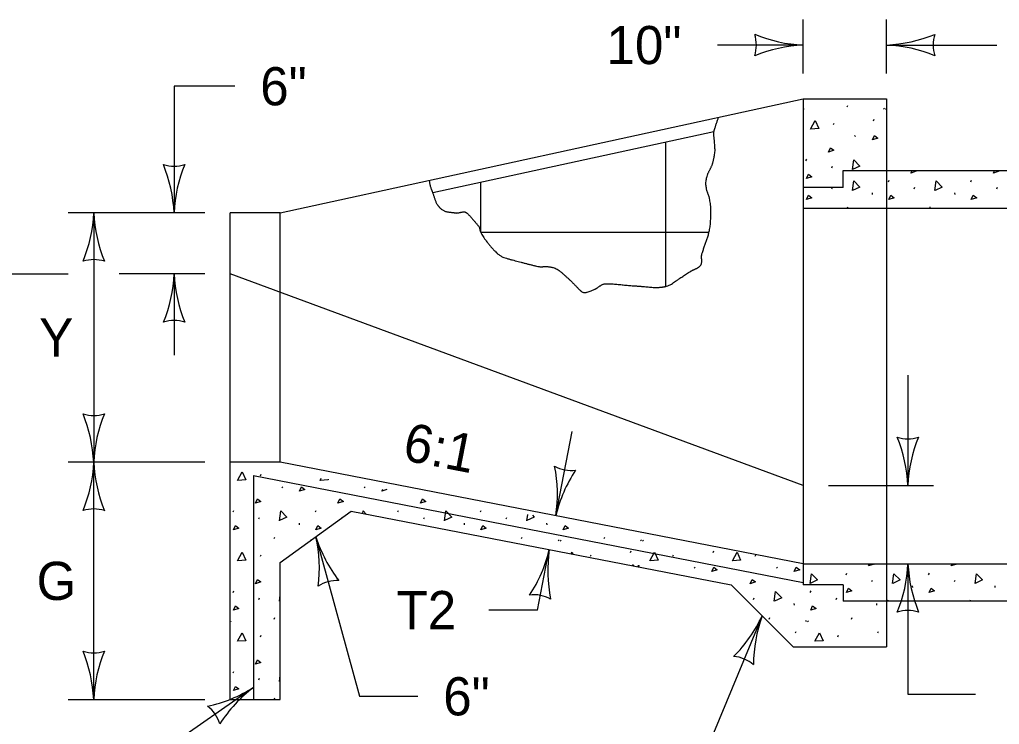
# Model space of a CAD drawing. Extents: x 49991.4 to 50043, y 49987.6 to 50011.4.
# Drawn here: x 50002.892 to 50004.432, y 49997.154 to 49998.262 of the extents above; entities that cross this region are included whole.
import ezdxf

# ---------------------------------------------------------------- set-up
doc = ezdxf.new("R2010")
doc.units = 0
for name, color, linetype in [('Level 1', 7, 'Continuous'), ('Level 2', 7, 'Continuous'), ('Level 3', 7, 'Continuous'), ('Level 4', 7, 'Continuous')]:
    doc.layers.add(name, color=color, linetype=linetype)

msp = doc.modelspace()

# ---------------------------------------------------------------- linework, layer by layer
at = {"layer": 'Level 1'}
for p, q in [((50003.3015, 49997.9582), (50004.1233, 49998.1373)), ((50004.1233, 49998.1373), (50004.2543, 49998.1373)), ((50004.1233, 49998.1373), (50004.1233, 49997.3739)), ((50004.2543, 49998.1373), (50004.2543, 49997.2761)), ((50004.1233, 49998.1222), (50004.1244, 49998.1206)), ((50004.1926, 49998.1248), (50004.1936, 49998.1272)), ((50004.2498, 49998.1228), (50004.2509, 49998.1212)), ((50004.2529, 49998.1222), (50004.254, 49998.1206)), ((50004.2341, 49998.1031), (50004.2352, 49998.1055)), ((50004.171, 49998.097), (50004.1721, 49998.0994)), ((50003.9832, 49998.0858), (50003.5411, 49997.9898)), ((50004.2043, 49998.0799), (50004.2054, 49998.0783)), ((50003.9068, 49998.0692), (50003.9068, 49997.8425)), ((50004.1278, 49998.0402), (50004.1289, 49998.0426)), ((50004.1683, 49998.0293), (50004.1694, 49998.0317)), ((50004.1865, 49997.9984), (50004.1865, 49998.0246)), ((50004.1865, 49998.0246), (50004.877, 49998.0246)), ((50003.6164, 49998.0056), (50003.6164, 49997.9281)), ((50004.1865, 49997.9984), (50004.1233, 49997.9984)), ((50004.1683, 49997.9963), (50004.1693, 49997.9984)), ((50004.2574, 49998.0072), (50004.2585, 49998.0096)), ((50004.2979, 49997.9963), (50004.299, 49997.9987)), ((50004.3871, 49998.0072), (50004.3881, 49998.0096)), ((50004.4275, 49997.9963), (50004.4286, 49997.9987)), ((50004.2317, 49997.9896), (50004.2319, 49997.9872)), ((50004.3613, 49997.9896), (50004.3615, 49997.9872)), ((50004.9129, 49997.9654), (50004.1233, 49997.9654)), ((50004.1926, 49997.9654), (50004.1936, 49997.9678)), ((50004.3222, 49997.9654), (50004.3232, 49997.9678)), ((50003.2228, 49997.1935), (50003.2228, 49997.9582)), ((50003.3015, 49997.9582), (50003.2228, 49997.9582)), ((50003.6164, 49997.9281), (50003.9754, 49997.9281)), ((50002.638, 49997.8625), (50002.9684, 49997.8625)), ((50004.1233, 49997.5297), (50003.2228, 49997.8625)), ((50003.3015, 49997.5663), (50003.2228, 49997.5663)), ((50004.1233, 49997.4069), (50003.3015, 49997.5663)), ((50003.2594, 49997.5453), (50004.1233, 49997.3773)), ((50003.2594, 49997.5453), (50003.2594, 49997.1935)), ((50003.2705, 49997.545), (50003.2716, 49997.5474)), ((50003.3038, 49997.5279), (50003.3049, 49997.5263)), ((50003.4334, 49997.5279), (50003.4345, 49997.5263)), ((50003.2273, 49997.4882), (50003.2284, 49997.4906)), ((50003.3015, 49997.4089), (50003.413, 49997.4895)), ((50003.3569, 49997.4882), (50003.358, 49997.4906)), ((50003.413, 49997.4895), (50004.0102, 49997.3737)), ((50003.4866, 49997.4882), (50003.4876, 49997.4906)), ((50003.6162, 49997.4882), (50003.6172, 49997.4906)), ((50003.2678, 49997.4773), (50003.2689, 49997.4797)), ((50003.398, 49997.4787), (50003.3985, 49997.4797)), ((50003.527, 49997.4773), (50003.5281, 49997.4797)), ((50003.6567, 49997.4773), (50003.6577, 49997.4797)), ((50003.3312, 49997.4706), (50003.3314, 49997.4682)), ((50003.5904, 49997.4706), (50003.5907, 49997.4682)), ((50003.72, 49997.4706), (50003.7203, 49997.4682)), ((50003.2921, 49997.4464), (50003.2931, 49997.4488)), ((50003.3493, 49997.4444), (50003.3497, 49997.4438)), ((50003.6809, 49997.4464), (50003.682, 49997.4488)), ((50003.7382, 49997.4444), (50003.7393, 49997.4428)), ((50003.7413, 49997.4438), (50003.7423, 49997.4422)), ((50003.8105, 49997.4464), (50003.8116, 49997.4488)), ((50003.8678, 49997.4444), (50003.8689, 49997.4428)), ((50003.8709, 49997.4438), (50003.8719, 49997.4422)), ((50003.8521, 49997.4246), (50003.8531, 49997.427)), ((50003.9817, 49997.4246), (50003.9828, 49997.427)), ((50003.2705, 49997.4185), (50003.2716, 49997.4209)), ((50003.7889, 49997.4185), (50003.79, 49997.4209)), ((50003.9186, 49997.4185), (50003.9196, 49997.4209)), ((50004.0482, 49997.4185), (50004.0492, 49997.4209)), ((50003.3015, 49997.1935), (50003.3015, 49997.4089)), ((50003.8553, 49997.4049), (50003.8555, 49997.4037)), ((50003.8573, 49997.4033), (50003.8553, 49997.4049)), ((50003.9519, 49997.4015), (50003.9529, 49997.3999)), ((50004.0815, 49997.4015), (50004.0825, 49997.3999)), ((50004.1233, 49997.4069), (50004.848, 49997.4069)), ((50004.191, 49997.3896), (50004.1921, 49997.392)), ((50004.2315, 49997.3787), (50004.2326, 49997.3811)), ((50004.3206, 49997.3896), (50004.3217, 49997.392)), ((50004.3611, 49997.3787), (50004.3622, 49997.3811)), ((50003.2273, 49997.3618), (50003.2284, 49997.3642)), ((50004.0102, 49997.3737), (50004.1075, 49997.2761)), ((50004.1865, 49997.3739), (50004.1233, 49997.3739)), ((50004.1346, 49997.3618), (50004.1357, 49997.3642)), ((50004.1865, 49997.3739), (50004.1865, 49997.3478)), ((50004.2949, 49997.372), (50004.2951, 49997.3696)), ((50004.4245, 49997.372), (50004.4247, 49997.3696)), ((50003.2678, 49997.3508), (50003.2689, 49997.3532)), ((50004.0455, 49997.3508), (50004.0466, 49997.3532)), ((50004.1751, 49997.3508), (50004.1762, 49997.3532)), ((50004.2558, 49997.3478), (50004.2568, 49997.3502)), ((50004.3854, 49997.3478), (50004.3864, 49997.3502)), ((50004.1088, 49997.3442), (50004.1091, 49997.3418)), ((50004.8771, 49997.3478), (50004.1865, 49997.3478)), ((50004.2385, 49997.3442), (50004.2387, 49997.3418)), ((50003.2921, 49997.3199), (50003.2931, 49997.3223)), ((50004.0697, 49997.3199), (50004.0708, 49997.3223)), ((50004.127, 49997.3179), (50004.1281, 49997.3163)), ((50004.1301, 49997.3173), (50004.1312, 49997.3157)), ((50004.1994, 49997.3199), (50004.2004, 49997.3223)), ((50003.2234, 49997.3164), (50003.2239, 49997.3157)), ((50003.2705, 49997.2921), (50003.2716, 49997.2945)), ((50004.1113, 49997.2982), (50004.1124, 49997.3006)), ((50004.1778, 49997.2921), (50004.1788, 49997.2945)), ((50004.2409, 49997.2982), (50004.242, 49997.3006)), ((50004.1075, 49997.2761), (50004.2543, 49997.2761)), ((50003.2273, 49997.2353), (50003.2284, 49997.2377)), ((50003.2678, 49997.2244), (50003.2689, 49997.2268)), ((50003.2921, 49997.1935), (50003.2931, 49997.1959)), ((50003.2228, 49997.1935), (50003.3015, 49997.1935))]:
    msp.add_line(p, q, dxfattribs=at)
for points in [[(50004.135, 49998.0898), (50004.1422, 49998.1034), (50004.1478, 49998.0908), (50004.1353, 49998.0898)], [(50004.2323, 49998.073), (50004.2355, 49998.0797), (50004.2408, 49998.0757), (50004.2323, 49998.073)], [(50004.163, 49998.0539), (50004.1662, 49998.0606), (50004.1716, 49998.0566), (50004.163, 49998.0539)], [(50004.2007, 49998.0265), (50004.2028, 49998.0418), (50004.2124, 49998.0319), (50004.201, 49998.0266)], [(50004.1284, 49998.0123), (50004.1316, 49998.0189), (50004.1369, 49998.0149), (50004.1284, 49998.0123)], [(50004.2927, 49998.0209), (50004.2945, 49998.0246)], [(50004.2999, 49998.0246), (50004.3012, 49998.0236), (50004.2927, 49998.0209)], [(50004.4223, 49998.0209), (50004.4241, 49998.0246)], [(50004.4295, 49998.0246), (50004.4308, 49998.0236), (50004.4223, 49998.0209)], [(50004.2007, 49997.9935), (50004.2028, 49998.0088), (50004.2124, 49997.9989), (50004.201, 49997.9936)], [(50004.3303, 49997.9935), (50004.3325, 49998.0088), (50004.342, 49997.9989), (50004.3306, 49997.9936)], [(50004.1284, 49997.9793), (50004.1316, 49997.9859), (50004.1369, 49997.9819), (50004.1284, 49997.9793)], [(50004.258, 49997.9793), (50004.2612, 49997.9859), (50004.2665, 49997.9819), (50004.258, 49997.9793)], [(50004.3876, 49997.9793), (50004.3908, 49997.9859), (50004.3961, 49997.9819), (50004.3876, 49997.9793)], [(50003.2345, 49997.5378), (50003.2417, 49997.5514), (50003.2473, 49997.5388), (50003.2348, 49997.5378)], [(50003.3641, 49997.5378), (50003.366, 49997.5414)], [(50003.3766, 49997.5395), (50003.3769, 49997.5388), (50003.3644, 49997.5378)], [(50003.3318, 49997.521), (50003.335, 49997.5276), (50003.3403, 49997.5236), (50003.3318, 49997.521)], [(50003.4614, 49997.521), (50003.463, 49997.5243)], [(50003.4689, 49997.5233), (50003.4614, 49997.521)], [(50003.2625, 49997.5019), (50003.2657, 49997.5086), (50003.2711, 49997.5046), (50003.2625, 49997.5019)], [(50003.3922, 49997.5019), (50003.3954, 49997.5086), (50003.4007, 49997.5046), (50003.3922, 49997.5019)], [(50003.5218, 49997.5019), (50003.525, 49997.5086), (50003.5303, 49997.5046), (50003.5218, 49997.5019)], [(50003.3002, 49997.4745), (50003.3023, 49997.4898), (50003.3119, 49997.4799), (50003.3005, 49997.4746)], [(50003.4314, 49997.4859), (50003.432, 49997.4898), (50003.4367, 49997.4849)], [(50003.5595, 49997.4745), (50003.5616, 49997.4898), (50003.5711, 49997.4799), (50003.5597, 49997.4746)], [(50003.6891, 49997.4745), (50003.6904, 49997.4842)], [(50003.6978, 49997.483), (50003.7007, 49997.4799), (50003.6893, 49997.4746)], [(50003.2279, 49997.4602), (50003.2311, 49997.4669), (50003.2364, 49997.4629), (50003.2279, 49997.4602)], [(50003.3575, 49997.4602), (50003.3607, 49997.4669), (50003.366, 49997.4629), (50003.3575, 49997.4602)], [(50003.6167, 49997.4602), (50003.6199, 49997.4669), (50003.6252, 49997.4629), (50003.6167, 49997.4602)], [(50003.7463, 49997.4602), (50003.7495, 49997.4669), (50003.7548, 49997.4629), (50003.7463, 49997.4602)], [(50003.2345, 49997.4113), (50003.2417, 49997.4249), (50003.2473, 49997.4124), (50003.2348, 49997.4113)], [(50003.7589, 49997.4224), (50003.7602, 49997.4249), (50003.7615, 49997.4219)], [(50003.8826, 49997.4113), (50003.8898, 49997.4249), (50003.8954, 49997.4124), (50003.8829, 49997.4113)], [(50004.0122, 49997.4113), (50004.0194, 49997.4249), (50004.025, 49997.4124), (50004.0125, 49997.4113)], [(50003.9798, 49997.3945), (50003.983, 49997.4012), (50003.9883, 49997.3972), (50003.9798, 49997.3945)], [(50004.1094, 49997.3945), (50004.1126, 49997.4012), (50004.118, 49997.3972), (50004.1094, 49997.3945)], [(50004.2262, 49997.4033), (50004.2279, 49997.4069)], [(50004.2336, 49997.4069), (50004.2348, 49997.406), (50004.2262, 49997.4033)], [(50004.3559, 49997.4033), (50004.3576, 49997.4069)], [(50004.3632, 49997.4069), (50004.3644, 49997.406), (50004.3559, 49997.4033)], [(50003.2625, 49997.3755), (50003.2657, 49997.3822), (50003.2711, 49997.3782), (50003.2625, 49997.3755)], [(50004.0402, 49997.3755), (50004.0434, 49997.3822), (50004.0487, 49997.3782), (50004.0402, 49997.3755)], [(50004.1343, 49997.3759), (50004.1364, 49997.3912), (50004.146, 49997.3813), (50004.1346, 49997.376)], [(50004.2639, 49997.3759), (50004.266, 49997.3912), (50004.2756, 49997.3813), (50004.2642, 49997.376)], [(50004.3935, 49997.3759), (50004.3957, 49997.3912), (50004.4052, 49997.3813), (50004.3938, 49997.376)], [(50004.1916, 49997.3617), (50004.1948, 49997.3683), (50004.2001, 49997.3643), (50004.1916, 49997.3617)], [(50004.3212, 49997.3617), (50004.3244, 49997.3683), (50004.3297, 49997.3643), (50004.3212, 49997.3617)], [(50003.3002, 49997.3481), (50003.3015, 49997.3575)], [(50003.3015, 49997.3487), (50003.3005, 49997.3482)], [(50004.0779, 49997.3481), (50004.08, 49997.3633), (50004.0896, 49997.3535), (50004.0782, 49997.3482)], [(50003.2279, 49997.3338), (50003.2311, 49997.3405), (50003.2364, 49997.3365), (50003.2279, 49997.3338)], [(50004.1352, 49997.3338), (50004.1383, 49997.3405), (50004.1437, 49997.3365), (50004.1352, 49997.3338)], [(50003.2345, 49997.2849), (50003.2417, 49997.2985), (50003.2473, 49997.2859), (50003.2348, 49997.2849)], [(50004.1418, 49997.2849), (50004.149, 49997.2985), (50004.1546, 49997.2859), (50004.1421, 49997.2849)], [(50003.2625, 49997.249), (50003.2657, 49997.2557), (50003.2711, 49997.2517), (50003.2625, 49997.249)], [(50003.3002, 49997.2216), (50003.3015, 49997.2311)], [(50003.2279, 49997.2074), (50003.2311, 49997.214), (50003.2364, 49997.21), (50003.2279, 49997.2074)], [(50003.3015, 49997.2222), (50003.3005, 49997.2217)]]:
    msp.add_lwpolyline(points, dxfattribs=at)
msp.add_arc((50003.8648, 49997.4025), 0.00126, 318.786, 199.2662, dxfattribs=at)
msp.add_open_spline([(50003.5356, 49998.0092), (50003.5359, 49998.0075), (50003.5362, 49998.0057), (50003.5365, 49998.0039), (50003.5369, 49998.0015), (50003.5376, 49997.9991), (50003.5385, 49997.9968), (50003.5389, 49997.9956), (50003.5394, 49997.9945), (50003.5398, 49997.9933), (50003.5402, 49997.9922), (50003.5407, 49997.991), (50003.5411, 49997.9898), (50003.5419, 49997.9877), (50003.5425, 49997.9856), (50003.5432, 49997.9835), (50003.5439, 49997.9814), (50003.5446, 49997.9794), (50003.5454, 49997.9773), (50003.5462, 49997.9752), (50003.5472, 49997.9732), (50003.5484, 49997.9713), (50003.549, 49997.9703), (50003.5497, 49997.9694), (50003.5504, 49997.9685), (50003.5508, 49997.968), (50003.5512, 49997.9675), (50003.5516, 49997.9671), (50003.552, 49997.9666), (50003.5524, 49997.9662), (50003.5529, 49997.9657), (50003.5545, 49997.9641), (50003.5564, 49997.9629), (50003.5584, 49997.9619), (50003.5604, 49997.9609), (50003.5624, 49997.9603), (50003.5645, 49997.9599), (50003.5666, 49997.9596), (50003.5687, 49997.9593), (50003.5708, 49997.959), (50003.5718, 49997.9589), (50003.5729, 49997.9588), (50003.574, 49997.9587), (50003.575, 49997.9585), (50003.5761, 49997.9583), (50003.5771, 49997.9582), (50003.5786, 49997.958), (50003.5801, 49997.9582), (50003.5816, 49997.9584), (50003.5831, 49997.9586), (50003.5847, 49997.9591), (50003.5862, 49997.9593), (50003.5877, 49997.9596), (50003.5892, 49997.9597), (50003.5907, 49997.9597), (50003.5914, 49997.9597), (50003.592, 49997.9596), (50003.5927, 49997.9593), (50003.5934, 49997.959), (50003.594, 49997.9587), (50003.5946, 49997.9582), (50003.5967, 49997.9564), (50003.5986, 49997.9545), (50003.6004, 49997.9525), (50003.6022, 49997.9504), (50003.6038, 49997.9483), (50003.6056, 49997.9463), (50003.607, 49997.9448), (50003.6083, 49997.9432), (50003.6097, 49997.9416), (50003.611, 49997.9401), (50003.6123, 49997.9385), (50003.6136, 49997.9368), (50003.6141, 49997.9362), (50003.6144, 49997.9355), (50003.6146, 49997.9348), (50003.6148, 49997.9341), (50003.615, 49997.9333), (50003.6152, 49997.9326), (50003.6153, 49997.9318), (50003.6154, 49997.931), (50003.6156, 49997.9303), (50003.6158, 49997.9295), (50003.6161, 49997.9288), (50003.6164, 49997.9281), (50003.6182, 49997.9244), (50003.6203, 49997.921), (50003.6227, 49997.9177), (50003.6252, 49997.9143), (50003.6277, 49997.911), (50003.6303, 49997.9078), (50003.6335, 49997.9039), (50003.6369, 49997.9002), (50003.6405, 49997.8965), (50003.6422, 49997.8948), (50003.6441, 49997.8933), (50003.6462, 49997.8919), (50003.6482, 49997.8905), (50003.6504, 49997.8893), (50003.6527, 49997.8885), (50003.6572, 49997.887), (50003.6617, 49997.8855), (50003.6663, 49997.8843), (50003.6709, 49997.8831), (50003.6754, 49997.8819), (50003.68, 49997.8807), (50003.6848, 49997.8795), (50003.6897, 49997.8782), (50003.6945, 49997.877), (50003.6993, 49997.8758), (50003.7041, 49997.8747), (50003.709, 49997.8736), (50003.7099, 49997.8734), (50003.7107, 49997.8734), (50003.7116, 49997.8734), (50003.7125, 49997.8735), (50003.7134, 49997.8736), (50003.7143, 49997.8737), (50003.7152, 49997.8738), (50003.7161, 49997.874), (50003.7169, 49997.8741), (50003.7178, 49997.8742), (50003.7187, 49997.8742), (50003.7196, 49997.8741), (50003.7214, 49997.874), (50003.7231, 49997.8737), (50003.7249, 49997.8734), (50003.7267, 49997.8731), (50003.7284, 49997.8727), (50003.7301, 49997.8723), (50003.7336, 49997.8713), (50003.7369, 49997.8698), (50003.7398, 49997.8676), (50003.7436, 49997.8647), (50003.7471, 49997.8617), (50003.7505, 49997.8585), (50003.7539, 49997.8554), (50003.7572, 49997.8523), (50003.7605, 49997.8491), (50003.7617, 49997.8479), (50003.7629, 49997.8467), (50003.7641, 49997.8455), (50003.7653, 49997.8443), (50003.7664, 49997.843), (50003.7676, 49997.8417), (50003.7694, 49997.8399), (50003.7712, 49997.838), (50003.773, 49997.8363), (50003.7734, 49997.836), (50003.7737, 49997.8358), (50003.774, 49997.8355), (50003.7743, 49997.8352), (50003.7746, 49997.835), (50003.775, 49997.8347), (50003.7764, 49997.8337), (50003.778, 49997.8332), (50003.7796, 49997.8332), (50003.7814, 49997.8331), (50003.7832, 49997.8334), (50003.785, 49997.834), (50003.7886, 49997.8353), (50003.7921, 49997.8367), (50003.7956, 49997.8382), (50003.7963, 49997.8385), (50003.7971, 49997.8389), (50003.7978, 49997.8392), (50003.7985, 49997.8396), (50003.7992, 49997.8401), (50003.7999, 49997.8405), (50003.8013, 49997.8414), (50003.8026, 49997.8424), (50003.804, 49997.8434), (50003.8054, 49997.8443), (50003.8067, 49997.8451), (50003.8082, 49997.8458), (50003.8097, 49997.8465), (50003.8112, 49997.8469), (50003.8128, 49997.8469), (50003.8168, 49997.847), (50003.8208, 49997.8469), (50003.8248, 49997.8465), (50003.8287, 49997.8462), (50003.8327, 49997.8459), (50003.8367, 49997.8455), (50003.8407, 49997.8451), (50003.8447, 49997.8446), (50003.8487, 49997.8443), (50003.8527, 49997.844), (50003.8567, 49997.8437), (50003.8607, 49997.8434), (50003.8626, 49997.8433), (50003.8645, 49997.8432), (50003.8665, 49997.843), (50003.8684, 49997.8429), (50003.8703, 49997.8427), (50003.8722, 49997.8425), (50003.8761, 49997.8422), (50003.8799, 49997.8418), (50003.8838, 49997.8414), (50003.8876, 49997.8411), (50003.8915, 49997.841), (50003.8953, 49997.8411), (50003.8972, 49997.8412), (50003.8992, 49997.8413), (50003.9011, 49997.8416), (50003.902, 49997.8417), (50003.903, 49997.8418), (50003.9039, 49997.842), (50003.9044, 49997.842), (50003.9049, 49997.8421), (50003.9054, 49997.8422), (50003.9058, 49997.8423), (50003.9063, 49997.8424), (50003.9068, 49997.8425), (50003.9107, 49997.8435), (50003.9145, 49997.8453), (50003.9179, 49997.8475), (50003.9213, 49997.8498), (50003.9246, 49997.8521), (50003.928, 49997.8544), (50003.934, 49997.8584), (50003.94, 49997.8625), (50003.9461, 49997.8663), (50003.9473, 49997.8671), (50003.9487, 49997.8677), (50003.95, 49997.8684), (50003.9513, 49997.869), (50003.9527, 49997.8695), (50003.954, 49997.8701), (50003.9554, 49997.8707), (50003.9567, 49997.8714), (50003.9579, 49997.8721), (50003.9586, 49997.8725), (50003.9592, 49997.873), (50003.9598, 49997.8734), (50003.9601, 49997.8737), (50003.9604, 49997.8739), (50003.9607, 49997.8742), (50003.961, 49997.8745), (50003.9612, 49997.8747), (50003.9615, 49997.875), (50003.9625, 49997.8762), (50003.9633, 49997.8776), (50003.9636, 49997.8791), (50003.9639, 49997.8807), (50003.964, 49997.8822), (50003.9639, 49997.8838), (50003.9639, 49997.8854), (50003.9637, 49997.887), (50003.9637, 49997.8887), (50003.9637, 49997.8895), (50003.9637, 49997.8903), (50003.9638, 49997.891), (50003.9639, 49997.8918), (50003.964, 49997.8926), (50003.9642, 49997.8933), (50003.9651, 49997.8962), (50003.966, 49997.8991), (50003.967, 49997.902), (50003.968, 49997.9048), (50003.969, 49997.9077), (50003.9701, 49997.9106), (50003.9711, 49997.9134), (50003.972, 49997.9163), (50003.973, 49997.9192), (50003.974, 49997.9221), (50003.9747, 49997.9251), (50003.9754, 49997.9281), (50003.9772, 49997.9361), (50003.9779, 49997.9442), (50003.9782, 49997.9522), (50003.9785, 49997.9615), (50003.978, 49997.9709), (50003.9764, 49997.9801), (50003.9762, 49997.9815), (50003.9759, 49997.9828), (50003.9754, 49997.984), (50003.975, 49997.9853), (50003.9745, 49997.9866), (50003.974, 49997.9879), (50003.9736, 49997.9891), (50003.9731, 49997.9904), (50003.9726, 49997.9917), (50003.9721, 49997.9929), (50003.9718, 49997.9942), (50003.9716, 49997.9955), (50003.9704, 49998.0024), (50003.9707, 49998.0097), (50003.9726, 49998.0165), (50003.9731, 49998.0183), (50003.9737, 49998.02), (50003.9745, 49998.0216), (50003.9753, 49998.0233), (50003.9761, 49998.0249), (50003.977, 49998.0265), (50003.9778, 49998.0282), (50003.9786, 49998.0298), (50003.9794, 49998.0315), (50003.9803, 49998.0331), (50003.9808, 49998.0349), (50003.9813, 49998.0366), (50003.9818, 49998.0385), (50003.9823, 49998.0404), (50003.9827, 49998.0423), (50003.9831, 49998.0442), (50003.9836, 49998.0461), (50003.9839, 49998.048), (50003.9846, 49998.0519), (50003.985, 49998.0557), (50003.9848, 49998.0595), (50003.9846, 49998.0638), (50003.9842, 49998.068), (50003.9839, 49998.0722), (50003.9836, 49998.0768), (50003.9827, 49998.0814), (50003.9832, 49998.0859), (50003.9833, 49998.0864), (50003.9834, 49998.0869), (50003.9836, 49998.0874), (50003.9837, 49998.0878), (50003.9838, 49998.0883), (50003.984, 49998.0888), (50003.9842, 49998.0898), (50003.9845, 49998.0907), (50003.9848, 49998.0917), (50003.9854, 49998.0935), (50003.986, 49998.0954), (50003.9867, 49998.0973), (50003.9879, 49998.101), (50003.9892, 49998.1047), (50003.9905, 49998.1084)], degree=3, dxfattribs=at)
at = {"layer": 'Level 3'}
for p, q in [((50004.1233, 49998.1773), (50004.1233, 49998.262)), ((50004.2543, 49998.1773), (50004.2543, 49998.262)), ((50004.1233, 49998.222), (50003.989, 49998.222)), ((50004.2543, 49998.222), (50004.4277, 49998.222)), ((50003.1347, 49998.1573), (50003.1347, 49997.9582)), ((50003.2301, 49998.1573), (50003.1347, 49998.1573)), ((50003.1828, 49997.9582), (50002.9684, 49997.9582)), ((50003.0084, 49997.9582), (50003.0084, 49997.5663)), ((50003.1828, 49997.8625), (50003.0484, 49997.8625)), ((50003.1347, 49997.8625), (50003.1347, 49997.7345)), ((50004.288, 49997.7032), (50004.288, 49997.5297)), ((50003.7347, 49997.4823), (50003.7605, 49997.6149)), ((50003.1828, 49997.5663), (50002.9684, 49997.5663)), ((50003.0084, 49997.1935), (50003.0084, 49997.5663)), ((50004.1633, 49997.5297), (50004.328, 49997.5297)), ((50003.3573, 49997.4493), (50003.4261, 49997.1985)), ((50003.706, 49997.334), (50003.7244, 49997.4291)), ((50004.288, 49997.4069), (50004.288, 49997.202)), ((50003.706, 49997.334), (50003.6293, 49997.334)), ((50004.0589, 49997.3249), (50003.9572, 49997.08)), ((50003.2594, 49997.2124), (50003.1126, 49997.1102)), ((50003.4261, 49997.1985), (50003.5177, 49997.1985)), ((50004.288, 49997.202), (50004.3944, 49997.202)), ((50002.9684, 49997.1935), (50003.1828, 49997.1935))]:
    msp.add_line(p, q, dxfattribs=at)
for centre, radius, start, end in [((50004.1325, 49998.4442), 0.2223, 247.456, 267.6395), ((50003.9951, 49998.222), 0.0548, 342.1388, 17.8612), ((50004.2428, 49998.4547), 0.233, 272.8273, 292.0772), ((50004.3825, 49998.222), 0.0548, 162.1388, 197.8612), ((50004.1348, 49997.9893), 0.233, 92.8273, 112.0772), ((50004.2451, 49997.9999), 0.2223, 67.456, 87.6395), ((50003.1347, 49998.0864), 0.0548, 252.1388, 287.8612), ((50002.902, 49997.9467), 0.233, 2.8273, 22.0772), ((50003.3568, 49997.9491), 0.2223, 157.456, 177.6395), ((50002.7863, 49997.9674), 0.2223, 337.456, 357.6395), ((50003.2411, 49997.9697), 0.233, 182.8273, 202.0772), ((50003.0084, 49997.83), 0.0548, 72.1388, 107.8612), ((50002.9126, 49997.8717), 0.2223, 337.456, 357.6395), ((50003.3674, 49997.874), 0.233, 182.8273, 202.0772), ((50003.1347, 49997.7343), 0.0548, 72.1388, 107.8612), ((50003.0084, 49997.6945), 0.0548, 252.1388, 287.8612), ((50002.7757, 49997.5548), 0.233, 2.8273, 22.0772), ((50003.2305, 49997.5572), 0.2223, 157.456, 177.6395), ((50004.288, 49997.6579), 0.0548, 252.1388, 287.8612), ((50004.0553, 49997.5182), 0.233, 2.8273, 22.0772), ((50004.5101, 49997.5206), 0.2223, 157.456, 177.6395), ((50002.7863, 49997.5755), 0.2223, 337.456, 357.6395), ((50003.2411, 49997.5778), 0.233, 182.8273, 202.0772), ((50003.7592, 49997.6081), 0.0548, 241.1032, 276.8256), ((50003.5041, 49997.5156), 0.233, 351.7917, 11.0416), ((50003.9509, 49997.4308), 0.2223, 146.4204, 166.6039), ((50003.0084, 49997.4381), 0.0548, 72.1388, 107.8612), ((50003.1407, 49997.3993), 0.2223, 352.802, 12.9855), ((50003.5787, 49997.5219), 0.233, 198.1733, 217.4231), ((50003.5081, 49997.4803), 0.2223, 326.5057, 346.6892), ((50003.9551, 49997.3962), 0.233, 171.877, 191.1268), ((50004.0659, 49997.4161), 0.2223, 337.456, 357.6395), ((50004.5207, 49997.4184), 0.233, 182.8273, 202.0772), ((50003.3912, 49997.3256), 0.0548, 87.4848, 123.2072), ((50003.7, 49997.3033), 0.0548, 61.1885, 96.9109), ((50004.288, 49997.2787), 0.0548, 72.1388, 107.8612), ((50003.8572, 49997.4185), 0.2223, 314.9043, 335.0878), ((50004.2782, 49997.2463), 0.233, 160.2756, 179.5254), ((50003.0084, 49997.3217), 0.0548, 252.1388, 287.8612), ((50002.7757, 49997.182), 0.233, 2.8273, 22.0772), ((50003.2305, 49997.1844), 0.2223, 157.456, 177.6395), ((50004.0097, 49997.2065), 0.0548, 49.5871, 85.3095), ((50003.14, 49997.4), 0.2223, 282.3011, 302.4846), ((50003.4018, 49997.028), 0.233, 127.6724, 146.9222), ((50003.1542, 49997.1392), 0.0548, 16.9839, 52.7062)]:
    msp.add_arc(centre, radius, start, end, dxfattribs=at)
at = {"layer": 'Level 4'}
msp.add_line((50003.3015, 49997.5663), (50003.3015, 49997.9582), dxfattribs=at)

# ---------------------------------------------------------------- texts
at = {"layer": 'Level 2'}
for s, p in [('10"', (50003.8144, 49998.192)), ('6"', (50003.2701, 49998.1273)), ('Y', (50002.9227, 49997.7323)), ('G', (50002.9186, 49997.3499)), ('T2', (50003.4843, 49997.304)), ('6"', (50003.5577, 49997.1685))]:
    msp.add_text(s, height=0.06, dxfattribs=at).set_placement(p)
msp.add_text('6:1', height=0.06, rotation=349, dxfattribs=at).set_placement((50003.4919, 49997.5702))

doc.saveas('drawing.dxf')
